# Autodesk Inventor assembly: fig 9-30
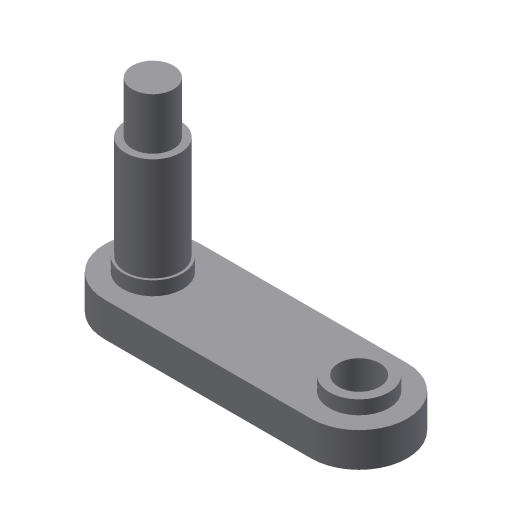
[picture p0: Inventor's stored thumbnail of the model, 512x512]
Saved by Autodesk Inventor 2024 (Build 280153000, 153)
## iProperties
Shininess: 64.0
Length Units: 11269
Angle Units: 11279
Time Units: 11290
Mass Units: 11283
Length Display Precision: 3
Angle Display Precision: 2
Created: 2002-01
Part Number: fig 9-30
Document SubType Name: Assembly
Designer: ***
Density: 0.0
Volumn: 0.0
Area: 0.0
PropertySet Name: Model Information
Control State: 0
Master: False
Checked Out: False
Author: ***
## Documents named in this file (3)
- D:\PROJECTS\Project 2023\RESOURCES INVENTOR 2024\RESOURCES INVENTOR 2024\Inventor_2023_Part\Inventor_2024_Part\c09_Inv_2024_prt\fig 9-34.iam
- D:\PROJECTS\Project 2023\RESOURCES INVENTOR 2024\RESOURCES INVENTOR 2024\Inventor_2023_Part\Inventor_2024_Part\c09_Inv_2024_prt\Part5.ipt
- D:\PROJECTS\Project 2023\RESOURCES INVENTOR 2024\RESOURCES INVENTOR 2024\Inventor_2023_Part\Inventor_2024_Part\c09_Inv_2024_prt\Part6.ipt
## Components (2 placed, 2 different names)
1. Part5:1 — Insert:1
2. Part6:1 — Insert:1
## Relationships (1: Insert 1)
- Insert:1: Part5:1 ↔ Part6:1
